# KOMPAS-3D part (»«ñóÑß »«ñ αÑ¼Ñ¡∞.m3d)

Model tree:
1. Эскиз:1
2. Операция выдавливания:1
     Расстояние 1 = 15
3. Эскиз:2
4. Вырезать элемент выдавливания:1
     Расстояние 1 = 20
5. Эскиз:3
6. Вырезать элемент выдавливания:2
     Расстояние 1 = 20
7. Эскиз:4
8. Вырезать элемент выдавливания:3
     Расстояние 1 = 3; Угол 1 = 27
9. Скругление:1
     Радиус = 1
10. Скругление:2
     Радиус = 1
11. Скругление:3
     Радиус = 1
12. Скругление:4
     Радиус = 1
13. Скругление:5
     Радиус = 1
14. Скругление:6
     Радиус = 1
15. Скругление:7
     Радиус = 1
16. Скругление:8
     Радиус = 1
17. Эскиз:5
18. Вырезать элемент выдавливания:4
     Расстояние 1 = 43
